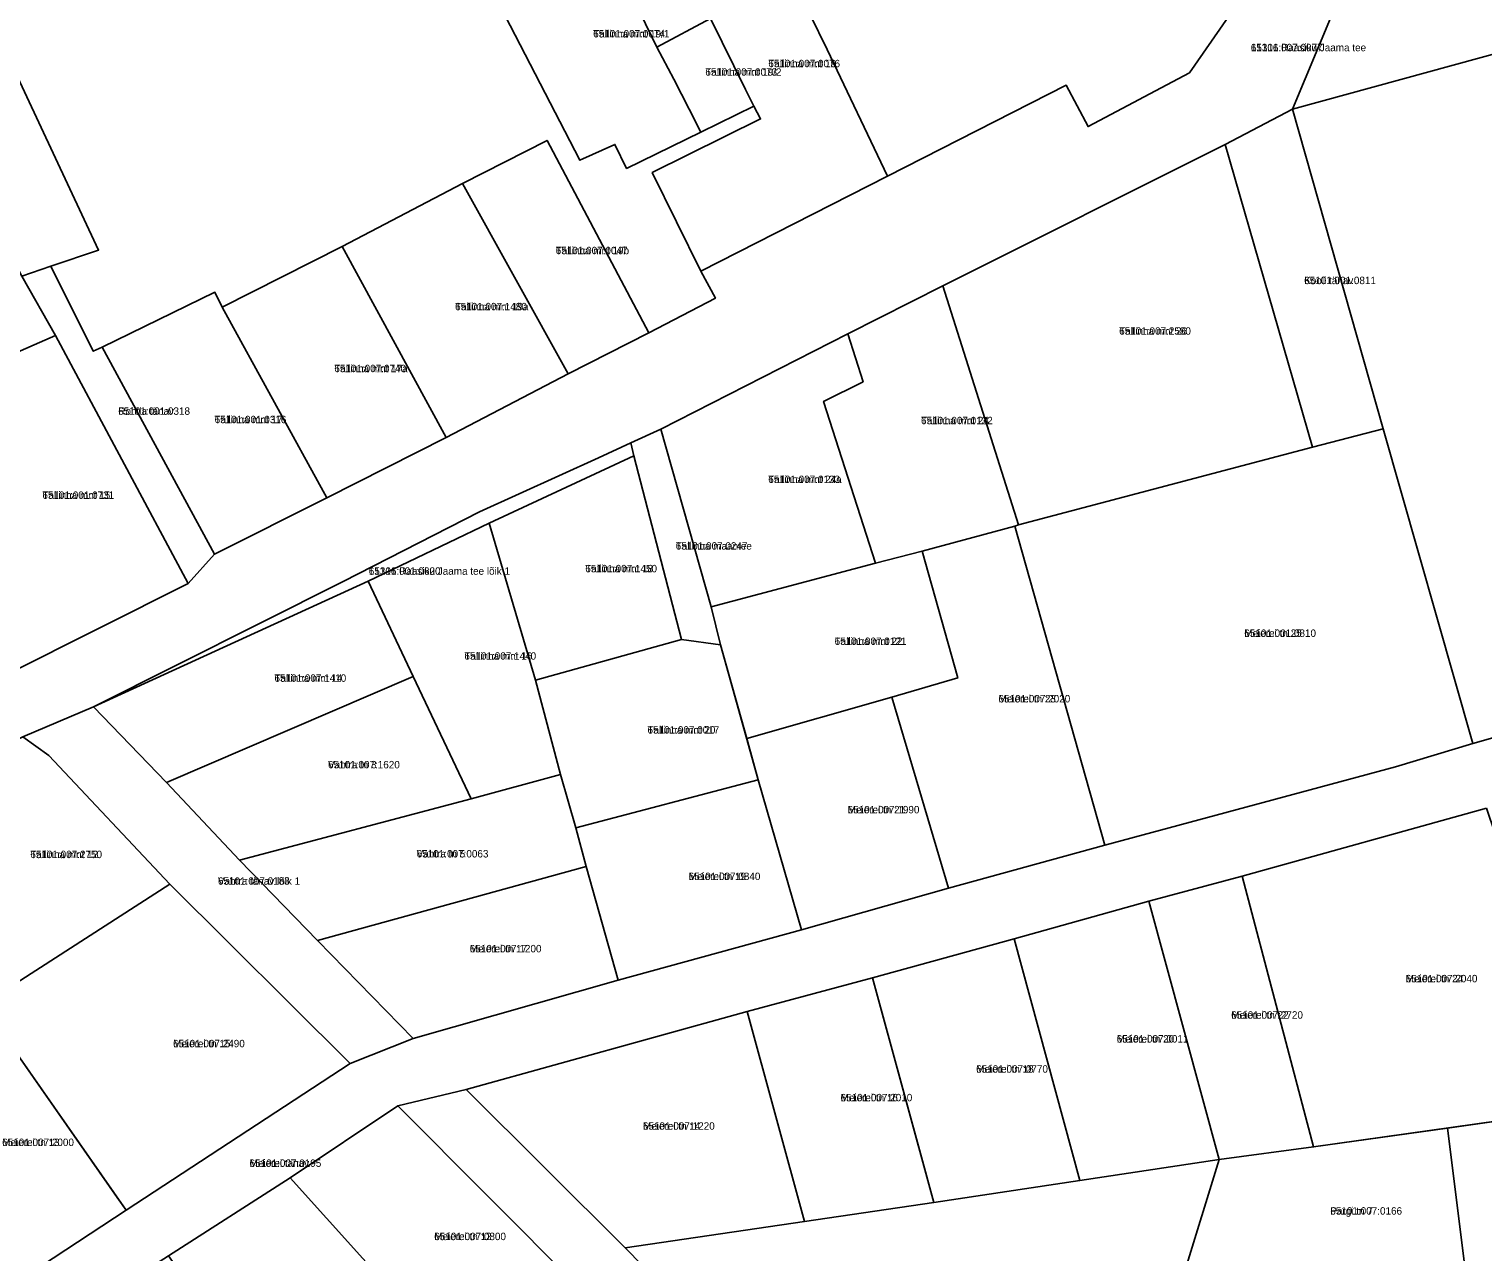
# Model space of a CAD drawing. Extents: x 556044 to 574504, y 6567077 to 6586269.
# Drawn here: x 567080 to 567373.8, y 6581628.6 to 6581875.7 of the extents above; entities that cross this region are included whole.
import ezdxf

# ---------------------------------------------------------------- set-up
doc = ezdxf.new("R2010")
doc.units = 0
for name, color, linetype in [('L_AADRESS', 7, 'Continuous'), ('PIIR', 7, 'Continuous'), ('TUNNUS', 7, 'Continuous')]:
    doc.layers.add(name, color=color, linetype=linetype)

msp = doc.modelspace()

# ---------------------------------------------------------------- linework, layer by layer
at = {"layer": 'PIIR'}
for points in [[(567014.26, 6582001.46), (567093.99, 6581831.04), (567084.34, 6581827.81), (567078.5, 6581825.81), (567077.82, 6581827.05), (567067.02, 6581825.68), (567025.69, 6581841.32), (567006.04, 6581848.76), (566993.17, 6581853.62), (566992.17, 6581852.82), (566966.02, 6581831.93), (566962.55, 6581829.16), (566951.98, 6581841.96), (566931.5, 6581866.86), (566914.02, 6581888.06), (566893.65, 6581912.75), (566866.32, 6581945.94), (566885.12, 6581950.36), (566940.48, 6581973.7), (566992.88, 6581993.38)], [(567270.92, 6581955.13), (567281.67, 6581960.47), (567323.94, 6581880.53), (567314.44, 6581866.86), (567293.98, 6581856.01), (567289.56, 6581864.36), (567253.46, 6581846.01), (567241.23, 6581871.6), (567237.82, 6581878.61), (567243.2, 6581881.25), (567239.66, 6581888.53), (567236.87, 6581894.25), (567234.05, 6581892.86), (567230.76, 6581899.52), (567223.74, 6581913.26), (567205.24, 6581903.53), (567217.69, 6581877.83), (567206.81, 6581872.06), (567194.34, 6581897.8), (567187.51, 6581913.79), (567266.1, 6581952.74)], [(567629.72, 6581940.2), (567638.16, 6581907.83), (567649.99, 6581862.47), (567619.51, 6581856.01), (567590.65, 6581847.86), (567562.39, 6581840.49), (567575.65, 6581784.96), (567484.74, 6581762.54), (567471.97, 6581811.83), (567426.35, 6581800.07), (567434.22, 6581749.07), (567371.73, 6581731.37), (567353.62, 6581794.95), (567335.32, 6581859.5)], [(567223.74, 6581913.26), (567230.76, 6581899.52), (567234.05, 6581892.86), (567236.87, 6581894.25), (567239.66, 6581888.53), (567243.2, 6581881.25), (567237.82, 6581878.61), (567241.23, 6581871.6), (567253.46, 6581846.01), (567215.72, 6581826.79), (567205.88, 6581846.7), (567227.8, 6581857.56), (567226.44, 6581860.16), (567224.73, 6581863.52), (567217.69, 6581877.83), (567205.24, 6581903.53)], [(567194.34, 6581897.8), (567206.81, 6581872.06), (567210.28, 6581865.59), (567213.38, 6581859.56), (567215.74, 6581854.88), (567200.71, 6581847.55), (567198.35, 6581852.42), (567191.26, 6581849.22), (567172.19, 6581886.16)], [(567217.69, 6581877.83), (567224.73, 6581863.52), (567226.44, 6581860.16), (567215.74, 6581854.88), (567213.38, 6581859.56), (567210.28, 6581865.59), (567206.81, 6581872.06)], [(567339.34, 6581791.21), (567321.68, 6581852.4), (567335.32, 6581859.5), (567353.62, 6581794.95)], [(567188.89, 6581806.02), (567167.55, 6581844.5), (567184.64, 6581853.21), (567205.23, 6581814.3)], [(567264.62, 6581823.8), (567321.68, 6581852.4), (567339.34, 6581791.21), (567279.91, 6581775.5)], [(567167.55, 6581844.5), (567188.89, 6581806.02), (567164.28, 6581793.15), (567143.2, 6581831.8)], [(567024.66, 6581838.61), (567025.69, 6581841.32), (567067.02, 6581825.68), (567077.82, 6581827.05), (567078.5, 6581825.81), (567085.27, 6581813.81), (567053.22, 6581799.79), (567032.95, 6581790.96), (567006.37, 6581779.12), (567003.58, 6581783.03)], [(567118.99, 6581819.54), (567143.2, 6581831.8), (567164.28, 6581793.15), (567140.15, 6581781.01)], [(567085.27, 6581813.81), (567078.5, 6581825.81), (567084.34, 6581827.81), (567092.94, 6581810.62), (567094.74, 6581811.45), (567117.46, 6581769.59), (567112.08, 6581763.71)], [(567117.46, 6581769.59), (567094.74, 6581811.45), (567117.52, 6581822.55), (567118.99, 6581819.54), (567140.15, 6581781.01)], [(567245.42, 6581814.14), (567264.62, 6581823.8), (567279.91, 6581775.5), (567279.15, 6581775.28), (567260.47, 6581770.2), (567251.04, 6581767.77), (567240.52, 6581800.46), (567248.52, 6581804.46)], [(567075.74, 6581745.41), (567053.22, 6581799.79), (567085.27, 6581813.81), (567112.08, 6581763.71)], [(567207.63, 6581794.86), (567245.42, 6581814.14), (567248.52, 6581804.46), (567240.52, 6581800.46), (567251.04, 6581767.77), (567217.78, 6581758.98)], [(567202.19, 6581789.5), (567172.93, 6581775.85), (567148.49, 6581764.16), (567092.97, 6581738.78), (567143.4, 6581764.08), (567171, 6581778.16), (567195, 6581789.1), (567201.56, 6581792.09)], [(567201.56, 6581792.09), (567207.63, 6581794.86), (567217.78, 6581758.98), (567219.71, 6581751.3), (567211.78, 6581752.37), (567202.19, 6581789.5)], [(567297.39, 6581710.83), (567279.15, 6581775.28), (567279.91, 6581775.5), (567339.34, 6581791.21), (567353.62, 6581794.95), (567371.73, 6581731.37), (567356.11, 6581726.65)], [(567211.78, 6581752.37), (567182.27, 6581744.16), (567172.93, 6581775.85), (567202.19, 6581789.5)], [(567172.93, 6581775.85), (567182.27, 6581744.16), (567187.37, 6581725.11), (567169.33, 6581720.16), (567157.57, 6581744.86), (567148.49, 6581764.16)], [(567297.39, 6581710.83), (567265.79, 6581702.12), (567254.34, 6581740.71), (567267.65, 6581744.6), (567260.47, 6581770.2), (567279.15, 6581775.28)], [(567217.78, 6581758.98), (567251.04, 6581767.77), (567260.47, 6581770.2), (567267.65, 6581744.6), (567254.34, 6581740.71), (567225, 6581732.33), (567219.71, 6581751.3)], [(567107.71, 6581723.46), (567092.97, 6581738.78), (567148.49, 6581764.16), (567157.57, 6581744.86)], [(567211.78, 6581752.37), (567219.71, 6581751.3), (567227.32, 6581723.99), (567190.48, 6581714.3), (567187.37, 6581725.11), (567182.27, 6581744.16)], [(567107.71, 6581723.46), (567157.57, 6581744.86), (567169.33, 6581720.16), (567122.46, 6581707.77)], [(567225, 6581732.33), (567254.34, 6581740.71), (567265.79, 6581702.12), (567236.08, 6581693.66), (567227.32, 6581723.99)], [(567078.69, 6581732.69), (567092.97, 6581738.78), (567107.71, 6581723.46), (567122.46, 6581707.77), (567138.26, 6581691.51), (567157.57, 6581671.76), (567144.85, 6581666.66), (567108.42, 6581702.89), (567083.94, 6581728.92)], [(567052.48, 6581718.38), (567051.97, 6581719.68), (567078.69, 6581732.69), (567083.94, 6581728.92), (567108.42, 6581702.89), (567075.23, 6581681.57)], [(567122.46, 6581707.77), (567169.33, 6581720.16), (567187.37, 6581725.11), (567190.48, 6581714.3), (567192.56, 6581706.51), (567138.26, 6581691.51)], [(567192.56, 6581706.51), (567190.48, 6581714.3), (567227.32, 6581723.99), (567236.08, 6581693.66), (567199.02, 6581683.51)], [(567374.48, 6581718.3), (567376.27, 6581713.09), (567391.21, 6581657.13), (567339.55, 6581649.81), (567325.12, 6581704.5)], [(567157.57, 6581671.76), (567138.26, 6581691.51), (567192.56, 6581706.51), (567199.02, 6581683.51)], [(567325.12, 6581704.5), (567339.55, 6581649.81), (567320.49, 6581647.25), (567306.26, 6581699.46)], [(567144.85, 6581666.66), (567099.59, 6581637.02), (567097.77, 6581639.62), (567070.56, 6581678.54), (567075.23, 6581681.57), (567108.42, 6581702.89)], [(567306.26, 6581699.46), (567320.47, 6581647.26), (567292.28, 6581643.06), (567279.05, 6581691.89)], [(567279.05, 6581691.89), (567292.28, 6581643.06), (567262.82, 6581638.62), (567250.44, 6581683.96)], [(567250.44, 6581683.96), (567260.32, 6581647.76), (567262.82, 6581638.62), (567236.66, 6581634.77), (567225.07, 6581677.21)], [(567077.58, 6581622.54), (567049.44, 6581664.62), (567052.39, 6581666.53), (567070.56, 6581678.54), (567099.59, 6581637.02)], [(567225.07, 6581677.21), (567236.66, 6581634.77), (567200.45, 6581629.4), (567168.28, 6581661.43)], [(567154.47, 6581658.14), (567190.94, 6581621.55), (567169.41, 6581602.79), (567132.73, 6581643.59)], [(567315.49, 6581512.18), (567334.96, 6581538.08), (567355.32, 6581567.95), (567359.48, 6581574.07), (567366.19, 6581593.15), (567372.11, 6581609.97), (567371.02, 6581618.65), (567366.61, 6581653.63), (567391.21, 6581657.13), (567396.85, 6581609.93), (567392.35, 6581593.39), (567383.79, 6581567.57), (567373.67, 6581548.26), (567363.02, 6581530.31), (567334.34, 6581493.11)], [(567320.47, 6581647.26), (567339.55, 6581649.81), (567366.61, 6581653.63), (567371.02, 6581618.65), (567313.38, 6581624.3)], [(567200.45, 6581629.4), (567236.66, 6581634.77), (567262.82, 6581638.62), (567292.28, 6581643.06), (567320.47, 6581647.26), (567313.38, 6581624.3), (567306.28, 6581601.35), (567299.18, 6581578.4), (567292.07, 6581555.45), (567334.96, 6581538.08), (567315.49, 6581512.18)], [(567132.73, 6581643.59), (567169.41, 6581602.79), (567152.7, 6581587.99), (567127.51, 6581576.8), (567128.27, 6581599.18), (567108.11, 6581627.8)]]:
    msp.add_lwpolyline(points, close=True, dxfattribs=at)
for points in [[(567172.19, 6581886.16), (567191.26, 6581849.22), (567198.35, 6581852.42), (567200.71, 6581847.55), (567215.74, 6581854.88), (567226.44, 6581860.16), (567227.8, 6581857.56), (567205.88, 6581846.7), (567215.72, 6581826.79), (567218.67, 6581821.36), (567205.23, 6581814.3), (567184.64, 6581853.21), (567167.55, 6581844.5), (567143.2, 6581831.8), (567118.99, 6581819.54), (567117.52, 6581822.55), (567094.74, 6581811.45), (567092.94, 6581810.62), (567084.34, 6581827.81), (567093.99, 6581831.04), (567014.26, 6582001.46)], [(567629.72, 6581940.2), (567335.32, 6581859.5), (567343.29, 6581878.7)], [(566854.58, 6581638.07), (566878.02, 6581649.75), (566925.86, 6581672.72), (566949.96, 6581684.44), (566974.51, 6581696.39), (567006.11, 6581711.87), (567032.2, 6581724.55), (567057.87, 6581736.37), (567075.74, 6581745.41), (567112.08, 6581763.71), (567117.46, 6581769.59), (567140.15, 6581781.01), (567164.28, 6581793.15), (567188.89, 6581806.02), (567205.23, 6581814.3), (567218.67, 6581821.36), (567215.72, 6581826.79), (567253.46, 6581846.01), (567289.56, 6581864.36), (567293.98, 6581856.01), (567314.44, 6581866.86), (567323.94, 6581880.53)], [(567343.29, 6581878.7), (567335.32, 6581859.5), (567321.68, 6581852.4), (567264.62, 6581823.8), (567245.42, 6581814.14), (567207.63, 6581794.86), (567201.56, 6581792.09), (567195, 6581789.1), (567171, 6581778.16), (567143.4, 6581764.08), (567092.97, 6581738.78), (567078.69, 6581732.69), (567051.97, 6581719.68), (567052.48, 6581718.38), (567028.28, 6581705.9), (567005.45, 6581694.93), (566954.49, 6581670.99), (566912.04, 6581650.08), (566903.42, 6581645.98), (566880.35, 6581635.22), (566854.57, 6581622.56)], [(566867.31, 6581506.14), (566883.3, 6581503.67), (566902.2, 6581507.27), (566919.12, 6581517.92), (566918.6, 6581518.7), (566970.04, 6581553.01), (566974.46, 6581556.22), (567013.09, 6581581), (567036.65, 6581596.08), (567056.01, 6581608.51), (567077.58, 6581622.54), (567099.59, 6581637.02), (567144.85, 6581666.66), (567157.57, 6581671.76), (567199.02, 6581683.51), (567236.08, 6581693.66), (567265.79, 6581702.12), (567297.39, 6581710.83), (567356.11, 6581726.65), (567371.73, 6581731.37), (567434.22, 6581749.07)], [(567374.48, 6581718.3), (567325.12, 6581704.5), (567306.26, 6581699.46), (567279.05, 6581691.89), (567250.44, 6581683.96), (567225.07, 6581677.21), (567168.28, 6581661.43), (567154.47, 6581658.14), (567132.73, 6581643.59), (567108.11, 6581627.8), (567085.44, 6581613.26), (567061.12, 6581597.61), (567001.81, 6581557.4), (566978.5, 6581541.73), (566954.26, 6581525.74), (566915.51, 6581499.92), (566917.8, 6581497.62), (566928.98, 6581495.85), (566926.09, 6581477.65), (566926.27, 6581467.58), (566867.87, 6581479.18)], [(567382.58, 6581440.11), (567373, 6581438.51), (567344.09, 6581466.95), (567338.61, 6581472.69), (567324.3, 6581485.79), (567304.52, 6581507.32), (567253.54, 6581559.23), (567219.22, 6581593.28), (567190.94, 6581621.55), (567154.47, 6581658.14), (567168.28, 6581661.43), (567200.45, 6581629.4), (567315.49, 6581512.18), (567334.34, 6581493.11), (567352.02, 6581476.04), (567372.26, 6581453.88), (567376.17, 6581450.8)]]:
    msp.add_lwpolyline(points, dxfattribs=at)

# ---------------------------------------------------------------- texts
at = {"layer": 'L_AADRESS'}
for s, p in [('Tallinna mnt 19/1', (567193.96, 6581874.02)), ('11316 Raasiku Jaama tee', (567326.86, 6581871.24)), ('Tallinna mnt 19', (567229.35, 6581868.01)), ('Tallinna mnt 19/2', (567216.62, 6581866.29)), ('Tallinna mnt 19b', (567186.39, 6581830.22)), ('Kooli tänav', (567337.65, 6581824.17)), ('Tallinna mnt 19a', (567166.05, 6581818.89)), ('Tallinna mnt 26', (567300.26, 6581813.95)), ('Tallinna mnt 17a', (567141.64, 6581806.38)), ('Rohtla tänav', (567097.98, 6581797.77)), ('Tallinna mnt 17', (567117.45, 6581796.07)), ('Tallinna mnt 24', (567260.21, 6581795.86)), ('Tallinna mnt 24a', (567229.34, 6581783.98)), ('Tallinna mnt 15', (567082.65, 6581780.78)), ('Tallinna maantee', (567210.64, 6581770.52)), ('11316 Raasiku Jaama tee lõik 1', (567148.61, 6581765.44)), ('Tallinna mnt 18', (567192.36, 6581765.94)), ('Meierei tn 25', (567325.54, 6581752.89)), ('Tallinna mnt 22', (567242.75, 6581751.26)), ('Tallinna mnt 16', (567167.93, 6581748.28)), ('Tallinna mnt 14', (567129.55, 6581743.81)), ('Meierei tn 23', (567275.87, 6581739.64)), ('Tallinna mnt 20', (567204.94, 6581733.34)), ('Vahtra tn 3', (567140.38, 6581726.32)), ('Meierei tn 21', (567245.39, 6581717.23)), ('Vahtra tn 5', (567158.29, 6581708.31)), ('Tallinna mnt 12', (567080.2, 6581708.18)), ('Vahtra tänav lõik 1', (567118.13, 6581702.8)), ('Meierei tn 19', (567213.25, 6581703.75)), ('Meierei tn 17', (567169.01, 6581689.14)), ('Meierei tn 24', (567358.16, 6581683.09)), ('Meierei tn 22', (567322.9, 6581675.74)), ('Meierei tn 20', (567299.76, 6581670.91)), ('Meierei tn 15', (567109.05, 6581669.96)), ('Meierei tn 18', (567271.36, 6581664.83)), ('Meierei tn 16', (567243.95, 6581659.04)), ('Meierei tn 14', (567204.02, 6581653.3)), ('Meierei tn 13', (567074.52, 6581650)), ('Meierei tänav', (567124.51, 6581645.79)), ('Pargi tn 7', (567342.93, 6581636.14)), ('Meierei tn 12', (567161.83, 6581630.98))]:
    msp.add_text(s, height=1.5, dxfattribs=at).set_placement(p)
at = {"layer": 'TUNNUS'}
for s, p in [('65101:007:0074', (567193.96, 6581874.02)), ('65101:007:0077', (567326.86, 6581871.24)), ('65101:007:0076', (567229.35, 6581868.01)), ('65101:007:0073', (567216.62, 6581866.29)), ('65101:007:0047', (567186.39, 6581830.22)), ('65101:001:0811', (567337.65, 6581824.17)), ('65101:007:1480', (567166.05, 6581818.89)), ('65101:007:2580', (567300.26, 6581813.95)), ('65101:007:0740', (567141.64, 6581806.38)), ('65101:001:0318', (567097.98, 6581797.77)), ('65101:001:0316', (567117.45, 6581796.07)), ('65101:007:0132', (567260.21, 6581795.86)), ('65101:007:0133', (567229.34, 6581783.98)), ('65101:001:0731', (567082.65, 6581780.78)), ('65101:007:0247', (567210.64, 6581770.52)), ('65101:001:0620', (567148.61, 6581765.44)), ('65101:007:1450', (567192.36, 6581765.94)), ('65101:001:0810', (567325.54, 6581752.89)), ('65101:007:0121', (567242.75, 6581751.26)), ('65101:007:1440', (567167.93, 6581748.28)), ('65101:007:1410', (567129.55, 6581743.81)), ('65101:007:2020', (567275.87, 6581739.64)), ('65101:007:0017', (567204.94, 6581733.34)), ('65101:007:1620', (567140.38, 6581726.32)), ('65101:007:1990', (567245.39, 6581717.23)), ('65101:007:0063', (567158.29, 6581708.31)), ('65101:007:2750', (567080.2, 6581708.18)), ('65101:007:0183', (567118.13, 6581702.8)), ('65101:007:0840', (567213.25, 6581703.75)), ('65101:007:1200', (567169.01, 6581689.14)), ('65101:007:2040', (567358.16, 6581683.09)), ('65101:007:2720', (567322.9, 6581675.74)), ('65101:007:0011', (567299.76, 6581670.91)), ('65101:007:2490', (567109.05, 6581669.96)), ('65101:007:0770', (567271.36, 6581664.83)), ('65101:007:2010', (567243.95, 6581659.04)), ('65101:007:1220', (567204.02, 6581653.3)), ('65101:007:2000', (567074.52, 6581650)), ('65101:007:0195', (567124.51, 6581645.79)), ('65101:007:0166', (567342.93, 6581636.14)), ('65101:007:0800', (567161.83, 6581630.98))]:
    msp.add_text(s, height=1.5, dxfattribs=at).set_placement(p)

doc.saveas('drawing.dxf')
